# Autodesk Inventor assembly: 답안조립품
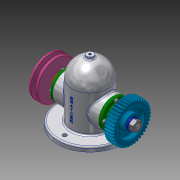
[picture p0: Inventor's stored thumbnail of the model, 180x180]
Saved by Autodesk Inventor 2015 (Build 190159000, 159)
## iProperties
Created: 2019-11
Part Number: 답안조립품
Document SubType Name: Assembly
Designer: LINEART-SSD.D4.16.05
Author: LINEART-SSD.D4.16.05
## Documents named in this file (14)
- C:\Users\LINEART-SSD.D4.16.05\Desktop\491104V1016\답안조립품.iam
- C:\Users\LINEART-SSD.D4.16.05\Desktop\491104V1016\본체.ipt
- C:\Users\LINEART-SSD.D4.16.05\Desktop\491104V1016\491104V1016\축.ipt
- C:\Users\LINEART-SSD.D4.16.05\Desktop\491104V1016\491104V1016\베어링 6203.ipt
- C:\Users\LINEART-SSD.D4.16.05\Desktop\491104V1016\491104V1016\키 5x5x12.ipt
- C:\Users\LINEART-SSD.D4.16.05\Desktop\491104V1016\491104V1016\커버.ipt
- C:\Users\LINEART-SSD.D4.16.05\Desktop\491104V1016\491104V1016\부시.ipt
- C:\Users\LINEART-SSD.D4.16.05\Desktop\491104V1016\491104V1016\오일 실 26 38 8.ipt
- C:\Users\LINEART-SSD.D4.16.05\Desktop\491104V1016\491104V1016\볼트 M4.ipt
- C:\Users\LINEART-SSD.D4.16.05\Desktop\491104V1016\491104V1016\스퍼기어.ipt
- C:\Users\LINEART-SSD.D4.16.05\Desktop\491104V1016\491104V1016\너트 M12x1.25.ipt
- C:\Users\LINEART-SSD.D4.16.05\Desktop\491104V1016\491104V1016\와셔 12x24.ipt
- C:\Users\LINEART-SSD.D4.16.05\Desktop\491104V1016\491104V1016\V-벨트풀리.ipt
- V-벨트풀리.ipt
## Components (1 placed, 1 different names)
1. V-벨트풀리:1 — 각도:5
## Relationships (1: Angle 1)
- 각도:5 [Angle]: V-벨트풀리:1
